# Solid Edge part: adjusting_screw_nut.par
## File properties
Title: Adjusting screw nut
Author: vicky raina
Template: Normal.par
Last saved by: Robert a Rhodes jr
Revision: 6
Application: Solid Edge
Material: aluminum
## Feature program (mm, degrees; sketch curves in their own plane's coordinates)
sketch for "unnamed RevolvedProtrusion 1" plane through (0, 0, 0) normal (0, -1, 0) x-axis (1, 0, 0)
  line (25.4, 9.7462) -> (74.676, 9.7462)
  line (76.2, 8.2222) -> (74.676, 9.7462)
  line (76.2, -26.8298) -> (76.2, 8.2222)
  line (76.2, -26.8298) -> (74.676, -28.3538)
  line (74.676, -28.3538) -> (47.625, -28.3538)
  line (47.625, -28.3538) -> (47.625, -60.1038)
  line (47.625, -60.1038) -> (25.4, -60.1038)
  line (25.4, -60.1038) -> (25.4, 9.7462)
revolve "unnamed RevolvedProtrusion 1" add full turn 360 deg
sketch for "unnamed Hole 1" plane through (76.2, 0, 0) normal (1, 0, 0) x-axis (0, 1, 0)
  hole centre (0, -9.3038) bore radius 9.5123
hole "unnamed Hole 1" finite
pattern "unnamed Pattern 1" of "unnamed Hole 1"
pattern "unnamed Pattern 2"
sketch for "unnamed Cutout 1" plane through (0, 0, 9.7462) normal (0, 0, 1) x-axis (1, 0, 0)
extrude "unnamed Cutout 1" cut through along -normal
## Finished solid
Body 1: solid body, 16 faces, 16 edges, 4 vertices.
  Faces by surface: cylinder 7, cone 6, plane 3
  Edges by curve: circle 12, intersection 4
Bounding box of the edges (mm): 152.400 x 152.400 x 69.850, from (-76.2, -76.2, -60.1038) to (76.2, 76.2, 9.7462).
Cylindrical faces by radius (mm): R9.5123 x4, R38.1 x1, R47.625 x1, R76.2 x1
Conical faces (half-angle, radius in mm at the cone's reference point): 45 deg R74.676 x1, 45 deg R76.2 x1, 59 deg R9.5123 x4
Planar faces by outward normal: +z 1, -z 2
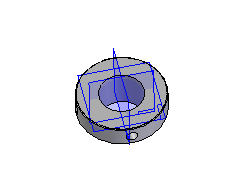
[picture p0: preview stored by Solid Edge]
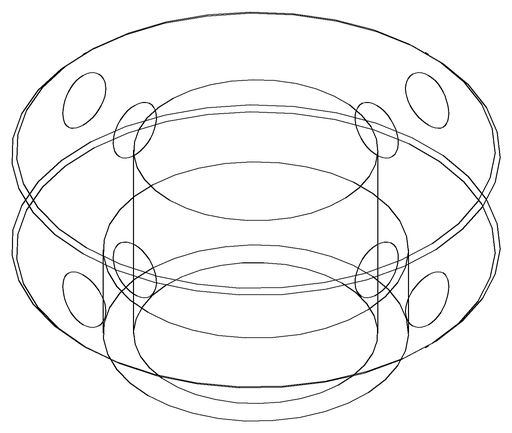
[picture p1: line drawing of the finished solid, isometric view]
